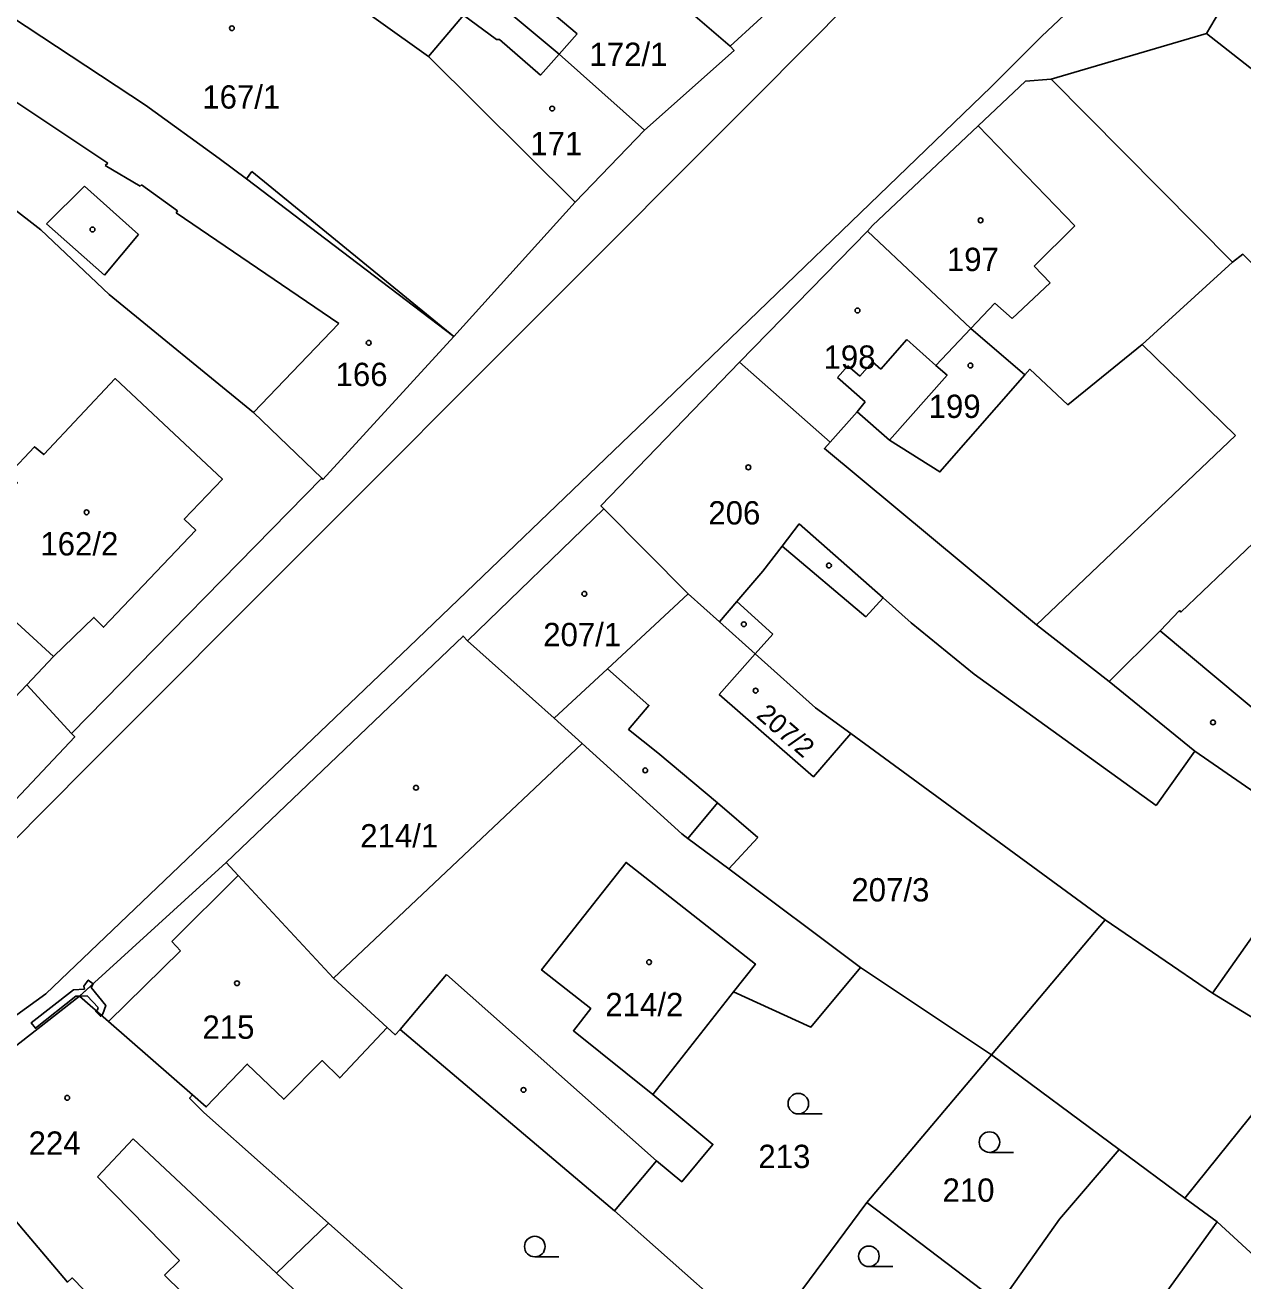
# Model space of a CAD drawing. Extents: x -600849 to -599899, y -1204328 to -1203436.
# Drawn here: x -600452.2 to -600363.4, y -1203727 to -1203635.4 of the extents above; entities that cross this region are included whole.
import ezdxf

# ---------------------------------------------------------------- set-up
doc = ezdxf.new("R2010")
doc.units = 0
for name, color, linetype in [('Vrstva 1', 7, 'Continuous'), ('Vrstva 13', 7, 'Continuous'), ('Vrstva 2', 7, 'Continuous'), ('Vrstva 3', 7, 'Continuous'), ('Vrstva 4', 7, 'Continuous'), ('Vrstva 5', 7, 'Continuous')]:
    doc.layers.add(name, color=color, linetype=linetype)

msp = doc.modelspace()

# ---------------------------------------------------------------- linework, layer by layer
at = {"layer": 'Vrstva 1'}
for p, q in [((-600400.8, -1203636.96), (-600389.19, -1203626.31)), ((-600361.42, -1203628.14), (-600366.05, -1203636.05)), ((-600443.46, -1203641.26), (-600455.29, -1203633.46)), ((-600366.05, -1203636.05), (-600377.39, -1203639.38)), ((-600366.05, -1203636.05), (-600359.62, -1203641.11)), ((-600377.39, -1203639.38), (-600379.25, -1203639.51)), ((-600364.16, -1203652.72), (-600377.39, -1203639.38)), ((-600438.07, -1203645.15), (-600443.46, -1203641.26)), ((-600412.1, -1203648.35), (-600407.05, -1203643.1)), ((-600420.96, -1203658.14), (-600412.1, -1203648.35)), ((-600390.78, -1203650.47), (-600400.12, -1203660.02)), ((-600390.42, -1203650.06), (-600390.78, -1203650.47)), ((-600390.78, -1203650.47), (-600383.26, -1203657.57)), ((-600383.26, -1203657.57), (-600379.3, -1203660.95)), ((-600400.12, -1203660.02), (-600393.52, -1203665.86)), ((-600448.84, -1203687.11), (-600430.59, -1203668.48)), ((-600410.01, -1203670.73), (-600419.97, -1203680.36)), ((-600410.01, -1203670.73), (-600403.87, -1203676.92)), ((-600450.16, -1203681.49), (-600457.99, -1203674.31)), ((-600403.87, -1203676.92), (-600409.76, -1203682.4)), ((-600452.11, -1203683.55), (-600450.16, -1203681.49)), ((-600448.84, -1203687.11), (-600452.11, -1203683.55)), ((-600392, -1203687.12), (-600373.45, -1203700.7)), ((-600400.91, -1203696.99), (-600403.88, -1203694.76)), ((-600357.88, -1203695.04), (-600365.63, -1203706.06)), ((-600437.57, -1203696.53), (-600448.26, -1203706.28)), ((-600391.29, -1203704.19), (-600400.91, -1203696.99)), ((-600373.45, -1203700.7), (-600381.74, -1203710.56)), ((-600373.45, -1203700.7), (-600365.63, -1203706.06)), ((-600381.74, -1203710.56), (-600391.29, -1203704.19)), ((-600448.26, -1203706.28), (-600459.42, -1203714.97)), ((-600400.55, -1203705.95), (-600406.44, -1203713.44)), ((-600381.74, -1203710.56), (-600390.84, -1203721.33)), ((-600381.74, -1203710.56), (-600372.42, -1203717.46)), ((-600390.84, -1203721.33), (-600398.42, -1203731.52)), ((-600390.84, -1203721.33), (-600381.13, -1203728.69)), ((-600409.24, -1203721.92), (-600398.42, -1203731.52))]:
    msp.add_line(p, q, dxfattribs=at)
for points in [[(-600468.32, -1203708.8), (-600459.02, -1203700.91), (-600447.7, -1203689.53), (-600398.8, -1203640.57), (-600381.76, -1203623.36), (-600376.64, -1203618.38), (-600366.85, -1203610.56), (-600358.79, -1203604.64), (-600335.27, -1203586.75), (-600326.92, -1203580.15), (-600315.47, -1203571.41), (-600313.87, -1203569.96), (-600309.19, -1203565.44), (-600307.64, -1203563.87), (-600297.75, -1203553.71), (-600294.09, -1203550.64), (-600277.89, -1203537.3), (-600263.22, -1203524.94), (-600248.8, -1203512.9), (-600231.21, -1203497.85)], [(-600516.74, -1203754.05), (-600500.93, -1203742.85), (-600482.23, -1203729.97), (-600472.33, -1203722.55), (-600463.46, -1203715.87), (-600456.83, -1203710.5), (-600450.71, -1203706.1), (-600424.21, -1203680.79), (-600406.92, -1203664.19), (-600381.77, -1203639.93), (-600378.09, -1203636.25), (-600365.25, -1203624.15), (-600362.86, -1203622.3), (-600356.33, -1203617.3), (-600346.34, -1203609.78), (-600334.21, -1203600.46), (-600309.35, -1203581.63), (-600259.57, -1203537.67), (-600253.46, -1203531.77)], [(-600407.05, -1203643.1), (-600413.28, -1203637.54), (-600418.97, -1203632.78), (-600426.95, -1203626.62), (-600434.28, -1203622.01)], [(-600416.14, -1203624.9), (-600413.77, -1203626.66), (-600406.75, -1203631.83), (-600400.8, -1203636.96)], [(-600437.73, -1203628.23), (-600429.94, -1203632.61), (-600422.81, -1203637.72), (-600412.1, -1203648.35)], [(-600400.8, -1203636.96), (-600400.52, -1203637.27), (-600407.05, -1203643.1)], [(-600379.25, -1203639.51), (-600382.71, -1203642.77), (-600390.42, -1203650.06)], [(-600430.59, -1203668.48), (-600435.56, -1203663.69), (-600446.11, -1203655.07), (-600451.09, -1203650.36), (-600457.96, -1203645.05)], [(-600420.96, -1203658.14), (-600436.09, -1203646.65), (-600438.07, -1203645.15)], [(-600352.14, -1203663.19), (-600363.4, -1203652.15), (-600364.16, -1203652.72)], [(-600379.3, -1203660.95), (-600378.94, -1203660.54), (-600376.17, -1203663.12), (-600370.74, -1203658.72), (-600364.16, -1203652.72)], [(-600430.59, -1203668.48), (-600430.51, -1203668.57), (-600420.96, -1203658.14)], [(-600389.18, -1203665.72), (-600384.98, -1203660.97), (-600385.79, -1203660.26), (-600383.26, -1203657.57)], [(-600400.12, -1203660.02), (-600410.23, -1203670.49), (-600410.01, -1203670.73)], [(-600457.99, -1203674.31), (-600452.79, -1203668.81), (-600453.42, -1203668.19), (-600451.54, -1203666.19), (-600450.87, -1203666.76), (-600445.65, -1203661.21), (-600437.84, -1203668.56), (-600440.62, -1203671.46), (-600439.79, -1203672.28), (-600446.52, -1203679.36), (-600447.21, -1203678.64), (-600450.16, -1203681.49)], [(-600389.18, -1203665.72), (-600385.5, -1203668.02), (-600379.3, -1203660.95)], [(-600393.52, -1203665.86), (-600391.54, -1203663.63), (-600389.18, -1203665.72)], [(-600373.17, -1203683.31), (-600369.43, -1203679.61), (-600368.04, -1203678.14), (-600367.92, -1203678.25), (-600363.2, -1203673.74), (-600352.14, -1203663.19)], [(-600393.52, -1203665.86), (-600393.93, -1203666.32), (-600378.47, -1203679.19), (-600373.17, -1203683.31)], [(-600452.11, -1203683.55), (-600462.69, -1203694.7), (-600470.65, -1203687.23), (-600465.44, -1203681.45), (-600466.1, -1203680.84), (-600464.04, -1203678.65), (-600463.39, -1203679.27), (-600460.4, -1203676.09)], [(-600403.87, -1203676.92), (-600401.58, -1203678.97), (-600398.97, -1203681.3)], [(-600419.97, -1203680.36), (-600420.29, -1203680), (-600437.57, -1203696.53)], [(-600403.88, -1203694.76), (-600404.34, -1203694.42), (-600411.59, -1203687.83), (-600413.64, -1203686), (-600419.97, -1203680.36)], [(-600392, -1203687.12), (-600394.73, -1203690.26), (-600401.6, -1203684.26), (-600398.97, -1203681.3)], [(-600398.97, -1203681.3), (-600394.58, -1203685.23), (-600392, -1203687.12)], [(-600409.76, -1203682.4), (-600406.73, -1203685.06), (-600408.21, -1203686.81), (-600406.08, -1203688.51), (-600401.72, -1203692.16), (-600398.79, -1203694.7), (-600400.91, -1203696.99)], [(-600373.17, -1203683.31), (-600366.91, -1203688.4), (-600362.52, -1203691.44)], [(-600460.04, -1203699.45), (-600448.61, -1203687.36), (-600448.84, -1203687.11)], [(-600437.57, -1203696.53), (-600436.69, -1203697.47), (-600429.73, -1203704.96), (-600425.82, -1203708.55)], [(-600406.44, -1203713.44), (-600412.24, -1203708.79), (-600410.97, -1203707.18), (-600414.56, -1203704.35), (-600408.39, -1203696.51), (-600398.96, -1203703.93), (-600400.55, -1203705.95)], [(-600391.29, -1203704.19), (-600394.91, -1203708.53), (-600400.55, -1203705.95)], [(-600448.26, -1203706.28), (-600446.14, -1203708.12), (-600440.01, -1203713.48)], [(-600365.63, -1203706.06), (-600363, -1203707.66), (-600361.09, -1203708.81), (-600361.02, -1203709.84), (-600356.07, -1203713.68), (-600348.91, -1203719.22)], [(-600440.01, -1203713.48), (-600439.02, -1203714.35), (-600436.03, -1203711.22), (-600433.36, -1203713.79), (-600430.57, -1203710.97), (-600429.28, -1203712.23), (-600425.82, -1203708.55)], [(-600425.82, -1203708.55), (-600425.25, -1203709.08), (-600424.88, -1203708.7), (-600409.24, -1203721.92)], [(-600440.01, -1203713.48), (-600440.23, -1203713.72), (-600439.19, -1203714.76), (-600430.1, -1203722.84), (-600422.09, -1203729.96), (-600408.22, -1203742.58)], [(-600406.44, -1203713.44), (-600402.06, -1203717.09), (-600404.34, -1203719.81), (-600406.17, -1203718.28), (-600409.24, -1203721.92)], [(-600459.42, -1203714.97), (-600452.35, -1203723.33), (-600449.14, -1203727.13), (-600448.79, -1203726.83), (-600431.48, -1203744.63), (-600426.82, -1203748.42), (-600419.28, -1203756.23), (-600409.09, -1203765.55), (-600409.58, -1203766.13)], [(-600372.42, -1203717.46), (-600376.77, -1203722.54), (-600381.13, -1203728.69)], [(-600372.42, -1203717.46), (-600367.63, -1203721.01), (-600365.29, -1203722.74), (-600360.15, -1203727.46), (-600357.54, -1203729.93)]]:
    msp.add_lwpolyline(points, dxfattribs=at)
at = {"layer": 'Vrstva 13'}
for points in [[(-600448.7, -1203705.8), (-600451.78, -1203708.21), (-600451.48, -1203708.61), (-600448.52, -1203706.28), (-600448.26, -1203706.28), (-600447.26, -1203705.37), (-600447.63, -1203705.1), (-600447.95, -1203705.53), (-600447.9, -1203705.75)], [(-600447.7, -1203706.24), (-600446.91, -1203707.09), (-600446.95, -1203707.26), (-600447.04, -1203707.34), (-600446.66, -1203707.67), (-600446.56, -1203707.57), (-600446.35, -1203706.95), (-600447.41, -1203705.65), (-600447.26, -1203705.37), (-600448.26, -1203706.28)], [(-600447.04, -1203707.34), (-600447.08, -1203707.38), (-600446.74, -1203707.74), (-600446.66, -1203707.67)]]:
    msp.add_lwpolyline(points, close=True, dxfattribs=at)
at = {"layer": 'Vrstva 3'}
for p, q in [((-600395.833, -1203714.86), (-600394.083, -1203714.86)), ((-600381.893, -1203717.67), (-600380.143, -1203717.67)), ((-600415.053, -1203725.29), (-600413.303, -1203725.29)), ((-600390.683, -1203726), (-600388.933, -1203726))]:
    msp.add_line(p, q, dxfattribs=at)
for centre in [(-600395.833, -1203714.11), (-600381.893, -1203716.92), (-600415.053, -1203724.54), (-600390.683, -1203725.25)]:
    msp.add_circle(centre, 0.75, dxfattribs=at)
at = {"layer": 'Vrstva 4'}
for p, q in [((-600415.38, -1203633.17), (-600411.97, -1203636.06)), ((-600420.26, -1203634.71), (-600422.81, -1203637.72)), ((-600417.85, -1203636.49), (-600420.26, -1203634.71)), ((-600411.97, -1203636.06), (-600413.28, -1203637.54)), ((-600417.64, -1203636.49), (-600417.85, -1203636.49)), ((-600414.64, -1203639.08), (-600417.64, -1203636.49)), ((-600446.2, -1203645.49), (-600458.12, -1203637.56)), ((-600413.28, -1203637.54), (-600414.64, -1203639.08)), ((-600375.66, -1203650.07), (-600382.71, -1203642.77)), ((-600446.39, -1203645.68), (-600446.2, -1203645.49)), ((-600443.84, -1203647.19), (-600446.39, -1203645.68)), ((-600435.69, -1203646.12), (-600436.09, -1203646.65)), ((-600435.69, -1203646.12), (-600420.96, -1203658.14)), ((-600450.66, -1203649.93), (-600447.91, -1203647.18)), ((-600447.91, -1203647.18), (-600443.95, -1203650.7)), ((-600443.73, -1203647.08), (-600443.84, -1203647.19)), ((-600441.12, -1203648.97), (-600443.73, -1203647.08)), ((-600441.21, -1203649.12), (-600441.12, -1203648.97)), ((-600446.45, -1203653.66), (-600450.66, -1203649.93)), ((-600429.35, -1203657.19), (-600441.21, -1203649.12)), ((-600443.95, -1203650.7), (-600446.45, -1203653.66)), ((-600378.64, -1203653.01), (-600375.66, -1203650.07)), ((-600377.46, -1203654.22), (-600378.64, -1203653.01)), ((-600380.24, -1203656.84), (-600377.46, -1203654.22)), ((-600383.26, -1203657.57), (-600381.49, -1203655.71)), ((-600381.49, -1203655.71), (-600380.24, -1203656.84)), ((-600435.56, -1203663.69), (-600429.35, -1203657.19)), ((-600387.92, -1203658.37), (-600389.82, -1203660.52)), ((-600385.79, -1203660.26), (-600387.92, -1203658.37)), ((-600363.94, -1203665.38), (-600370.74, -1203658.72)), ((-600390.42, -1203659.99), (-600391.35, -1203661.04)), ((-600389.82, -1203660.52), (-600390.42, -1203659.99)), ((-600392.21, -1203660.28), (-600392.97, -1203661.14)), ((-600391.35, -1203661.04), (-600392.21, -1203660.28)), ((-600392.97, -1203661.14), (-600390.96, -1203662.92)), ((-600390.96, -1203662.92), (-600391.54, -1203663.63)), ((-600378.47, -1203679.19), (-600363.94, -1203665.38)), ((-600397.02, -1203673.45), (-600395.76, -1203671.82)), ((-600395.76, -1203671.82), (-600389.65, -1203677.22)), ((-600398.43, -1203675.27), (-600397.02, -1203673.45)), ((-600397.02, -1203673.45), (-600390.91, -1203678.6)), ((-600400.31, -1203677.48), (-600398.43, -1203675.27)), ((-600390.91, -1203678.6), (-600389.65, -1203677.22)), ((-600389.65, -1203677.22), (-600387.59, -1203679.04)), ((-600401.58, -1203678.97), (-600400.31, -1203677.48)), ((-600400.31, -1203677.48), (-600397.69, -1203679.85)), ((-600387.59, -1203679.04), (-600383.01, -1203682.79)), ((-600397.69, -1203679.85), (-600398.97, -1203681.3)), ((-600359.32, -1203688.08), (-600369.43, -1203679.61)), ((-600409.76, -1203682.4), (-600413.64, -1203686)), ((-600383.01, -1203682.79), (-600369.73, -1203692.36)), ((-600429.73, -1203704.96), (-600411.59, -1203687.83)), ((-600369.73, -1203692.36), (-600366.91, -1203688.4)), ((-600401.72, -1203692.16), (-600403.88, -1203694.76)), ((-600441.54, -1203702.29), (-600436.69, -1203697.47)), ((-600446.14, -1203708.12), (-600440.9, -1203702.97)), ((-600440.9, -1203702.97), (-600441.54, -1203702.29)), ((-600424.88, -1203708.7), (-600421.5, -1203704.7)), ((-600421.5, -1203704.7), (-600410.07, -1203714.82)), ((-600359.72, -1203711.15), (-600367.63, -1203721.01)), ((-600410.07, -1203714.82), (-600406.17, -1203718.28)), ((-600444.36, -1203716.67), (-600446.96, -1203719.45)), ((-600433.89, -1203726.48), (-600444.36, -1203716.67)), ((-600446.96, -1203719.45), (-600440.98, -1203725.56)), ((-600430.1, -1203722.84), (-600433.89, -1203726.48)), ((-600365.29, -1203722.74), (-600372.65, -1203732.94)), ((-600440.98, -1203725.56), (-600442.07, -1203726.63)), ((-600442.07, -1203726.63), (-600422.71, -1203745.4)), ((-600426.13, -1203733.75), (-600433.89, -1203726.48))]:
    msp.add_line(p, q, dxfattribs=at)
at = {"layer": 'Vrstva 5'}
for centre in [(-600437.147, -1203635.659), (-600413.787, -1203641.519), (-600382.537, -1203649.669), (-600447.317, -1203650.339), (-600391.517, -1203656.249), (-600427.167, -1203658.609), (-600383.277, -1203660.259), (-600399.477, -1203667.689), (-600447.747, -1203670.969), (-600393.597, -1203674.849), (-600411.437, -1203676.919), (-600399.807, -1203679.139), (-600398.947, -1203683.979), (-600365.587, -1203686.299), (-600406.997, -1203689.799), (-600423.717, -1203691.069), (-600406.717, -1203703.789), (-600436.777, -1203705.329), (-600415.877, -1203713.109), (-600449.157, -1203713.689)]:
    msp.add_circle(centre, 0.175, dxfattribs=at)

# ---------------------------------------------------------------- texts
at = {"layer": 'Vrstva 2'}
for s, p in [('172/1', (-600411.068, -1203638.41)), ('167/1', (-600439.308, -1203641.52)), ('171', (-600415.385, -1203644.92)), ('197', (-600384.995, -1203653.37)), ('198', (-600393.995, -1203660.5)), ('166', (-600429.585, -1203661.76)), ('199', (-600386.325, -1203664.09)), ('206', (-600402.395, -1203671.86)), ('162/2', (-600451.118, -1203674.12)), ('207/1', (-600414.44, -1203680.74)), ('214/1', (-600427.788, -1203695.42)), ('207/3', (-600391.96, -1203699.36)), ('214/2', (-600409.908, -1203707.73)), ('215', (-600439.295, -1203709.38)), ('224', (-600451.975, -1203717.84)), ('213', (-600398.745, -1203718.81)), ('210', (-600385.315, -1203721.27))]:
    msp.add_text(s, height=1.7, dxfattribs=at).set_placement(p)
msp.add_text('207/2', height=1.4, rotation=319, dxfattribs=at).set_placement((-600398.969, -1203685.888))

doc.saveas('drawing.dxf')
